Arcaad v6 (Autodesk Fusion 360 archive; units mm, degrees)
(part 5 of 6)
sketch "Sketch11" plane through (6, 0, 0) normal (1, 0, 0) x axis (0, 0, -1)
  line L1 (-2.3267, -33.65) -> (31.3267, -33.65)
  line L2 (-6.5036, -29.6802) -> (-2.6802, -33.5036)
  line L3 (-6.65, 4.3267) -> (-6.65, -29.3267)
  line L4 (-2.6802, 8.5036) -> (-6.5036, 4.6802)
  line L5 (31.3267, 8.65) -> (-2.3267, 8.65)
  line L6 (35.5036, 4.6802) -> (31.6802, 8.5036)
  line L7 (35.65, -29.3267) -> (35.65, 4.3267)
  line L8 (31.6802, -33.5036) -> (35.5036, -29.6802)
  line L9 (287, -585) -> (-13, -585)
  line L10 (287, 15) -> (287, -585)
  line L11 (-13, 15) -> (287, 15)
  line L12 (-13, -585) -> (-13, 15)
  line L13 (21.8852, -461.493) -> (24.8497, -461.493)
  line L14 (24.0039, -461.493) -> (20.4822, -461.493)
  line L15 (24.0039, -465.6319) -> (24.0039, -461.493)
  line L16 (20.4822, -465.5926) -> (20.4822, -461.493)
  line L17 (24.0039, -535.3209) -> (24.0039, -465.6319)
  line L18 (20.4822, -535.3209) -> (20.4822, -461.493)
  line L19 (24.0039, -535.3209) -> (20.4822, -535.3209)
  line L20 (21.8852, -12.9676) -> (21.8852, -557.5324)
  line L21 (24.0039, -60) -> (24.0039, -461.493)
  line L22 (20.4822, -60) -> (20.4822, -461.493)
  line L23 (24.0039, -60) -> (20.4822, -60)
  line L24 (24.0039, -461.493) -> (24.0039, -465.6319)
  line L25 (137, -585) -> (137, 15)
  line L26 (253.5178, -60) -> (253.5178, -461.493)
  line L27 (249.9961, -60) -> (249.9961, -461.493)
  line L28 (249.9961, -60) -> (253.5178, -60)
  line L29 (249.9961, -535.3209) -> (249.9961, -465.6319)
  line L30 (253.5178, -535.3209) -> (253.5178, -461.493)
  line L31 (249.9961, -535.3209) -> (253.5178, -535.3209)
  line L32 (249.9961, -465.6319) -> (249.9961, -461.493)
  line L33 (24.8239, -60) -> (24.8239, -461.493)
  line L34 (18.7522, -60) -> (18.7522, -461.493)
  line L35 (18.7522, -60) -> (24.8239, -60)
  line L36 (24.8239, -535.3209) -> (24.8239, -465.6319)
  line L37 (24.8239, -461.493) -> (24.8239, -465.6319)
  line L38 (18.7522, -535.3209) -> (18.7522, -461.493)
  line L39 (18.7522, -535.3209) -> (24.8239, -535.3209)
  circle C1 centre (161.6956, -62.1445) radius 6.75
  circle C2 centre (200, -65) radius 6.75
  circle C3 centre (109.4135, -81.8008) radius 11.3847
  circle C4 centre (53.9141, -65.8527) radius 6.75
  circle C5 centre (259.5, -557.5) radius 2.5
  circle C6 centre (14.5, -557.5) radius 2.5
  circle C7 centre (259.5, -12.5) radius 11
  arc A1 centre (-2.3267, -33.15) radius 0.5 clockwise from (-2.3267, -33.65) to (-2.6802, -33.5036)
  arc A2 centre (-6.15, -29.3267) radius 0.5 clockwise from (-6.5036, -29.6802) to (-6.65, -29.3267)
  arc A3 centre (-6.15, 4.3267) radius 0.5 clockwise from (-6.65, 4.3267) to (-6.5036, 4.6802)
  arc A4 centre (-2.3267, 8.15) radius 0.5 clockwise from (-2.6802, 8.5036) to (-2.3267, 8.65)
  arc A5 centre (31.3267, 8.15) radius 0.5 clockwise from (31.3267, 8.65) to (31.6802, 8.5036)
  arc A6 centre (35.15, 4.3267) radius 0.5 clockwise from (35.5036, 4.6802) to (35.65, 4.3267)
  arc A7 centre (35.15, -29.3267) radius 0.5 clockwise from (35.65, -29.3267) to (35.5036, -29.6802)
  arc A8 centre (31.3267, -33.15) radius 0.5 clockwise from (31.6802, -33.5036) to (31.3267, -33.65)
  circle C8 centre (45.0775, -139.6703) radius 10
  circle C9 centre (90, -150) radius 10
  circle C10 centre (140.8153, -144.1327) radius 15
  circle C11 centre (130.6535, -184.5454) radius 10
  circle C12 centre (77.0561, -242.5691) radius 7
  circle C13 centre (116.4021, -275.0095) radius 10
  circle C14 centre (220.1507, -225.5922) radius 20
  circle C15 centre (207.9814, -331.3336) radius 20
  circle C16 centre (172.7099, -424.5516) radius 10
  circle C17 centre (125, -350) radius 20
  circle C18 centre (90, -400) radius 15
  circle C19 centre (51.7744, -504.4554) radius 10
  circle C20 centre (140, -490) radius 10
  circle C21 centre (227.7787, -494.7374) radius 10
  circle C22 centre (67.1409, -471.833) radius 20
  circle C23 centre (50.7881, -395.8727) radius 7
  circle C24 centre (140, -390) radius 7
  circle C25 centre (178.2661, -386.7903) radius 15
  circle C26 centre (220, -370) radius 10
  circle C27 centre (181.6604, -262.778) radius 10
  circle C28 centre (123.6741, -235.6181) radius 20
  circle C29 centre (45.7185, -314.2782) radius 10
  circle C30 centre (90.9515, -202.6198) radius 7
  circle C31 centre (227.7787, -136.25) radius 10
  circle C32 centre (182.0487, -124.3724) radius 7
  circle C33 centre (100, -120) radius 7
  circle C34 centre (187.43, -169.7572) radius 20
  circle C35 centre (48.535, -233.4303) radius 10
  circle C36 centre (80, -320) radius 10
  circle C37 centre (173.431, -222.7107) radius 10
  circle C38 centre (200, -300) radius 7
  circle C39 centre (210, -410) radius 7
  circle C40 centre (154.6891, -315.7507) radius 15
  circle C41 centre (60.2066, -358.0992) radius 20
  circle C42 centre (50.4667, -431.8087) radius 15
  circle C43 centre (105.4265, -496.3966) radius 7
  circle C44 centre (185.5991, -468.2067) radius 20
  circle C45 centre (120, -460) radius 7
  circle C46 centre (90, -440) radius 10
  circle C47 centre (135.1235, -425.1239) radius 15
  circle C48 centre (166.6949, -345.8239) radius 7
  circle C49 centre (224.2144, -445.9118) radius 10
  circle C50 centre (223.4596, -269.0631) radius 10
  circle C51 centre (156.0884, -281.9568) radius 7
  circle C52 centre (68.5668, -277.091) radius 15
  circle C53 centre (62.4153, -183.7959) radius 20
  circle C54 centre (230, -180) radius 7
  arc A9 centre (130, -60) radius 6.75 clockwise from (133.8909, -54.4843) to (135.5774, -56.198)
  arc A10 centre (139.0445, -51.0994) radius 6.1658 clockwise from (143.4776, -55.3848) to (135.5774, -56.198)
  arc A11 centre (137.0235, -58.095) radius 7 clockwise from (143.4776, -55.3848) to (134.8099, -64.7357)
  arc A12 centre (130, -60) radius 6.75 clockwise from (134.8099, -64.7357) to (131.7577, -53.4829)
  arc A13 centre (137.0235, -58.095) radius 7 clockwise from (131.7577, -53.4829) to (133.0091, -52.3605)
  arc A14 centre (139.0445, -51.0994) radius 6.1658 clockwise from (133.8909, -54.4843) to (133.0091, -52.3605)
  arc A15 centre (60, -60) radius 7 clockwise from (59.8886, -53.0009) to (65.2927, -55.4188)
  arc A16 centre (56.4567, -67.9193) radius 15.308 clockwise from (59.8886, -53.0009) to (65.2927, -55.4188)
  arc A17 centre (229.981, -95.1972) radius 4.0346 clockwise from (230.2254, -99.2244) to (234.0075, -95.452)
  arc A18 centre (218.2305, -83.4163) radius 19.8437 clockwise from (236.6864, -90.7071) to (234.0075, -95.452)
  arc A19 centre (218.9336, -99.9179) radius 20 clockwise from (236.6864, -90.7071) to (199.0414, -101.992)
  arc A20 centre (185.6453, -91.3697) radius 17.0965 clockwise from (199.0414, -101.992) to (174.847, -78.115)
  arc A21 centre (181.7869, -77.1992) radius 7 clockwise from (174.847, -78.115) to (175.6985, -73.7449)
  arc A22 centre (169.4716, -57.7139) radius 17.1979 clockwise from (181.2794, -70.2176) to (175.6985, -73.7449)
  arc A23 centre (181.7869, -77.1992) radius 7 clockwise from (181.2794, -70.2176) to (188.233, -74.4702)
  arc A24 centre (185.6453, -91.3697) radius 17.0965 clockwise from (188.233, -74.4702) to (202.297, -95.2441)
  arc A25 centre (218.2305, -83.4163) radius 19.8438 clockwise from (230.2254, -99.2244) to (202.297, -95.2441)
  arc A26 centre (143.5424, -81.8008) radius 8.9317 clockwise from (143.9431, -90.7235) to (151.1665, -86.4536)
  arc A27 centre (138.5677, -94.5944) radius 15 clockwise from (151.1665, -86.4536) to (127.5251, -104.7463)
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  point P37 (20.4822, -461.493)
  point P41 (20.4822, -461.493)
  point P38 (24.0039, -461.493)
  point P42 (24.0039, -461.493)
  point P44 (20.4822, -461.493)
  point P47 (20.4822, -461.493)
  point P51 (24.0039, -461.493)
  point P43 (24.0039, -465.6319)
  point P60 (249.9961, -465.6319)
  point P46 (24.0039, -535.3209)
  point P61 (249.9961, -535.3209)
  point P56 (253.5178, -461.493)
  point P48 (20.4822, -535.3209)
  point P62 (253.5178, -535.3209)
  point P58 (249.9961, -461.493)
  point P52 (24.0039, -60)
  point P59 (249.9961, -60)
  point P53 (20.4822, -60)
  point P57 (253.5178, -60)
  coincident P37 P41
  coincident P38 P42
  perpendicular L14 L15
  coincident P37 P44
  perpendicular L14 L16
  parallel L15 L17
  coincident P37 P47
  parallel L17 L18
  perpendicular L17 L19
  coincident P38 P51
  parallel L20 L21
  parallel L20 L22
  perpendicular L21 L23
  symmetric P43 L25 P60
  symmetric P46 L25 P61
  symmetric P47 L25 P56
  symmetric P48 L25 P62
  symmetric P51 L25 P58
  symmetric P52 L25 P59
  symmetric P53 L25 P57
  perpendicular L34 L35
  perpendicular L38 L39
  dimension "d72" = 0.82
  dimension "d73" = -1.73
  dimension "d74" = -0.82
  dimension "d75" = 0.82
  dimension "d76" = 1.73
extrude "Extrude10" cut sketch "Sketch11" profile of L13 L17 L18 L19 L20 L21 L22 L23 L24 L26 L27 L28 L29 L30 L31 L32 L33 L34 L35 L36 L37 L38 L39 against normal blind 6
extrude "Extrude9" cut sketch "Sketch11" profile of L13 L17 L18 L19 L20 L21 L22 L23 L24 against normal blind 6
offset_faces "OffsetFaces2" distance 5
fillet "Fillet3" radius 3
work_plane "WorkPlane3"
mirror "Mirror1"
extrude "Extrude4" add sketch "Sketch3" profile of L7 L9 L10 L11 L12 L13 L15 L16 L17 L18 L19 L20 L21 L22 L23 L24 to an object
sketch "Sketch12" plane through (0, 0, 0) normal (1, 0, 0) x axis (0, 0, -1)
  line L1 (249.9961, -535.3209) -> (249.9961, -60)
  line L2 (249.9961, -60) -> (253.5178, -60)
  line L3 (249.9961, -535.3209) -> (249.9961, -60)
  line L4 (253.5178, -535.3209) -> (249.9961, -535.3209)
  line L5 (253.5178, -60) -> (253.5178, -535.3209)
  line L6 (18.7522, -60) -> (24.8239, -60)
  line L7 (18.7522, -535.3209) -> (18.7522, -60)
  line L8 (24.8239, -535.3209) -> (18.7522, -535.3209)
  line L9 (24.8239, -60) -> (24.8239, -535.3209)
  line L10 (-13, -585) -> (287, -585)
  line L11 (-13, 15) -> (-13, -585)
  line L12 (287, 15) -> (-13, 15)
  line L13 (287, -585) -> (287, 15)
  line L14 (249.1761, -535.3209) -> (249.1761, -60)
  line L15 (255.2478, -60) -> (255.2478, -535.3209)
  line L16 (255.2478, -535.3209) -> (249.1761, -535.3209)
  line L17 (249.1761, -60) -> (255.2478, -60)
  circle C1 centre (161.6956, -62.1445) radius 6.75
  circle C2 centre (200, -65) radius 6.75
  circle C3 centre (109.4135, -81.8008) radius 11.3847
  circle C4 centre (53.9141, -65.8527) radius 6.75
  circle C5 centre (259.5, -557.5) radius 2.5
  circle C6 centre (14.5, -557.5) radius 2.5
  circle C7 centre (259.5, -12.5) radius 2.5
  circle C8 centre (14.5, -12.5) radius 2.5
  arc A1 centre (66.9916, -91.3697) radius 13.5324 clockwise from (56.1847, -83.2249) to (71.1139, -104.2589)
  arc A2 centre (56.4567, -67.9193) radius 15.308 clockwise from (56.1847, -83.2249) to (51.3106, -82.3364)
  arc A3 centre (59.2759, -95.0468) radius 15 clockwise from (71.1139, -104.2589) to (51.3106, -82.3364)
  arc A4 centre (230, -70) radius 6.75 clockwise from (234.5359, -65.0012) to (225.5131, -64.9572)
  arc A5 centre (227.8855, -62.8164) radius 7 clockwise from (220.9494, -63.7597) to (234.5359, -65.0012)
  arc A6 centre (218.2305, -83.4163) radius 19.8438 clockwise from (220.9494, -63.7597) to (225.5131, -64.9572)
  circle C9 centre (45.0775, -139.6703) radius 10
  circle C10 centre (90, -150) radius 10
  circle C11 centre (140.8153, -144.1327) radius 15
  circle C12 centre (130.6535, -184.5454) radius 10
  circle C13 centre (77.0561, -242.5691) radius 7
  circle C14 centre (116.4021, -275.0095) radius 10
  circle C15 centre (220.1507, -225.5922) radius 20
  circle C16 centre (207.9814, -331.3336) radius 20
  circle C17 centre (172.7099, -424.5516) radius 10
  circle C18 centre (125, -350) radius 20
  circle C19 centre (90, -400) radius 15
  circle C20 centre (51.7744, -504.4554) radius 10
  circle C21 centre (140, -490) radius 10
  circle C22 centre (227.7787, -494.7374) radius 10
  circle C23 centre (67.1409, -471.833) radius 20
  circle C24 centre (50.7881, -395.8727) radius 7
  circle C25 centre (140, -390) radius 7
  circle C26 centre (178.2661, -386.7903) radius 15
  circle C27 centre (220, -370) radius 10
  circle C28 centre (181.6604, -262.778) radius 10
  circle C29 centre (123.6741, -235.6181) radius 20
  circle C30 centre (45.7185, -314.2782) radius 10
  circle C31 centre (90.9515, -202.6198) radius 7
  circle C32 centre (227.7787, -136.25) radius 10
  circle C33 centre (182.0487, -124.3724) radius 7
  circle C34 centre (100, -120) radius 7
  arc A7 centre (88.9999, -63.301) radius 6.75 clockwise from (82.2818, -63.9562) to (95.1111, -66.1673)
  arc A8 centre (87.4071, -72.5429) radius 10 clockwise from (77.4095, -72.3278) to (82.2818, -63.9562)
  arc A9 centre (81.2141, -77.1797) radius 6.1658 clockwise from (77.4095, -72.3278) to (84.7984, -82.1966)
  arc A10 centre (87.4071, -72.5429) radius 10 clockwise from (95.1111, -66.1673) to (84.7984, -82.1966)
  arc A11 centre (143.5424, -81.8008) radius 8.9317 clockwise from (143.9431, -90.7235) to (151.1665, -86.4536)
  arc A12 centre (126.5713, -87.0071) radius 17.7649 clockwise from (143.9431, -90.7235) to (127.5251, -104.7463)
  arc A13 centre (138.5677, -94.5944) radius 15 clockwise from (151.1665, -86.4536) to (127.5251, -104.7463)
  circle C35 centre (187.43, -169.7572) radius 20
  circle C36 centre (48.535, -233.4303) radius 10
  circle C37 centre (80, -320) radius 10
  circle C38 centre (173.431, -222.7107) radius 10
  circle C39 centre (200, -300) radius 7
  circle C40 centre (210, -410) radius 7
  circle C41 centre (154.6891, -315.7507) radius 15
  circle C42 centre (60.2066, -358.0992) radius 20
  circle C43 centre (50.4667, -431.8087) radius 15
  circle C44 centre (105.4265, -496.3966) radius 7
  circle C45 centre (185.5991, -468.2067) radius 20
  circle C46 centre (120, -460) radius 7
  circle C47 centre (90, -440) radius 10
  circle C48 centre (135.1235, -425.1239) radius 15
  circle C49 centre (166.6949, -345.8239) radius 7
  circle C50 centre (224.2144, -445.9118) radius 10
  circle C51 centre (223.4596, -269.0631) radius 10
  circle C52 centre (156.0884, -281.9568) radius 7
  circle C53 centre (68.5668, -277.091) radius 15
  circle C54 centre (62.4153, -183.7959) radius 20
  circle C55 centre (230, -180) radius 7
  arc A14 centre (229.981, -95.1972) radius 4.0346 clockwise from (230.2254, -99.2244) to (234.0075, -95.452)
  arc A15 centre (218.2305, -83.4163) radius 19.8438 clockwise from (230.2254, -99.2244) to (202.297, -95.2441)
  arc A16 centre (185.6453, -91.3697) radius 17.0965 clockwise from (188.233, -74.4702) to (202.297, -95.2441)
  arc A17 centre (181.7869, -77.1992) radius 7 clockwise from (181.2794, -70.2176) to (188.233, -74.4702)
  arc A18 centre (169.4716, -57.7139) radius 17.1979 clockwise from (181.2794, -70.2176) to (175.6985, -73.7449)
  arc A19 centre (181.7869, -77.1992) radius 7 clockwise from (174.847, -78.115) to (175.6985, -73.7449)
  arc A20 centre (185.6453, -91.3697) radius 17.0965 clockwise from (199.0414, -101.992) to (174.847, -78.115)
  arc A21 centre (218.9336, -99.9179) radius 20 clockwise from (236.6864, -90.7071) to (199.0414, -101.992)
  arc A22 centre (218.2305, -83.4163) radius 19.8438 clockwise from (236.6864, -90.7071) to (234.0075, -95.452)
  arc A23 centre (56.4567, -67.9193) radius 15.308 clockwise from (59.8886, -53.0009) to (65.2927, -55.4188)
  arc A24 centre (60, -60) radius 7 clockwise from (59.8886, -53.0009) to (65.2927, -55.4188)
  arc A25 centre (130, -60) radius 6.75 clockwise from (133.8909, -54.4843) to (135.5774, -56.198)
  arc A26 centre (139.0445, -51.0994) radius 6.1658 clockwise from (133.8909, -54.4843) to (133.0091, -52.3605)
  arc A27 centre (137.0235, -58.095) radius 7 clockwise from (131.7577, -53.4829) to (133.0091, -52.3605)
  arc A28 centre (130, -60) radius 6.75 clockwise from (134.8099, -64.7357) to (131.7577, -53.4829)
  arc A29 centre (137.0235, -58.095) radius 7 clockwise from (143.4776, -55.3848) to (134.8099, -64.7357)
  arc A30 centre (139.0445, -51.0994) radius 6.1658 clockwise from (143.4776, -55.3848) to (135.5774, -56.198)
  perpendicular L15 L16
  perpendicular L14 L17
  dimension "d77" = 0.82
  dimension "d78" = 1.73
extrude "Extrude11" cut sketch "Sketch12" profile of L1 L3 L5 L14 L15 L16 L17 along normal blind 6
sketch "Sketch1" plane through (0, 0, 0) normal (1, 0, 0) x axis (0, 1, 0)
  line L1
  line L2 (10.6725, 42.0131) -> (-11.493, 42.0131)
  line L3
  line L4 (-10.938, 45.9426) -> (-10.938, 45.9976)
  line L5 (10.6725, 49.1774) -> (10.6725, 46.7526)
  line L6 (10.6725, 44.9776) -> (10.6725, 42.0131)
  line L7 (-11.493, 42.0131) -> (-11.493, 44.9776)
  line L8 (-10.0325, 45.9976) -> (-10.0325, 45.9426)
  line L9 (-11.493, 46.7526) -> (-11.493, 49.1774)
  line L10 (-8.2175, 45.9976) -> (-8.2175, 45.9928)
  line L11 (-8.2175, 45.9928) -> (-8.723, 45.9928)
  line L12 (-8.723, 45.9928) -> (-8.723, 45.9976)
  line L13 (-10.2325, 45.9976) -> (-10.2325, 45.9928)
  line L14 (-10.2325, 45.9928) -> (-10.738, 45.9928)
  line L15 (-10.738, 45.9928) -> (-10.738, 45.9976)
  line L16 (-6.708, 45.9928) -> (-6.708, 45.9976)
  line L17 (-6.2025, 45.9976) -> (-6.2025, 45.9928)
  line L18 (-6.2025, 45.9928) -> (-6.708, 45.9928)
  line L19 (-4.693, 45.9928) -> (-4.693, 45.9976)
  line L20 (-4.1875, 45.9976) -> (-4.1875, 45.9928)
  line L21 (-4.1875, 45.9928) -> (-4.693, 45.9928)
  line L22 (-2.678, 45.9928) -> (-2.678, 45.9976)
  line L23 (-2.1725, 45.9976) -> (-2.1725, 45.9928)
  line L24 (-2.1725, 45.9928) -> (-2.678, 45.9928)
  line L25 (-0.663, 45.9928) -> (-0.663, 45.9976)
  line L26 (-0.1575, 45.9976) -> (-0.1575, 45.9928)
  line L27 (-0.1575, 45.9928) -> (-0.663, 45.9928)
  line L28 (1.352, 45.9928) -> (1.352, 45.9976)
  line L29 (1.8575, 45.9976) -> (1.8575, 45.9928)
  line L30 (1.8575, 45.9928) -> (1.352, 45.9928)
  line L31 (3.367, 45.9928) -> (3.367, 45.9976)
  line L32 (3.8725, 45.9976) -> (3.8725, 45.9928)
  line L33 (3.8725, 45.9928) -> (3.367, 45.9928)
  line L34 (5.382, 45.9928) -> (5.382, 45.9976)
  line L35 (5.8875, 45.9976) -> (5.8875, 45.9928)
  line L36 (5.8875, 45.9928) -> (5.382, 45.9928)
  line L37 (7.397, 45.9928) -> (7.397, 45.9976)
  line L38 (7.9025, 45.9976) -> (7.9025, 45.9928)
  line L39 (7.9025, 45.9928) -> (7.397, 45.9928)
  line L40 (9.412, 45.9928) -> (9.412, 45.9976)
  line L41 (9.9175, 45.9976) -> (9.9175, 45.9928)
  line L42 (9.9175, 45.9928) -> (9.412, 45.9928)
  line L43 (11.427, 45.9928) -> (11.427, 45.9976)
  arc A1 centre (-7.4625, 45.9976) radius 0.755 clockwise from (-8.2175, 45.9976) to (-7.4625, 46.7526)
  arc A2 centre (-9.478, 45.9976) radius 0.755 clockwise from (-9.478, 46.7526) to (-8.723, 45.9976)
  arc A3 centre (-9.4775, 45.9976) radius 0.755 clockwise from (-10.2325, 45.9976) to (-9.4777, 46.7526)
  arc A4 centre (-11.493, 45.9976) radius 0.755 clockwise from (-11.493, 46.7526) to (-10.738, 45.9976)
  arc A5 centre (-7.463, 45.9976) radius 0.755 clockwise from (-7.463, 46.7526) to (-6.708, 45.9976)
  arc A6 centre (-5.4475, 45.9976) radius 0.755 clockwise from (-6.2025, 45.9976) to (-5.4475, 46.7526)
  arc A7 centre (-5.448, 45.9976) radius 0.755 clockwise from (-5.448, 46.7526) to (-4.693, 45.9976)
  arc A8 centre (-3.4325, 45.9976) radius 0.755 clockwise from (-4.1875, 45.9976) to (-3.4325, 46.7526)
  arc A9 centre (-3.433, 45.9976) radius 0.755 clockwise from (-3.433, 46.7526) to (-2.678, 45.9976)
  arc A10 centre (-1.4175, 45.9976) radius 0.755 clockwise from (-2.1725, 45.9976) to (-1.4175, 46.7526)
  arc A11 centre (-1.418, 45.9976) radius 0.755 clockwise from (-1.418, 46.7526) to (-0.663, 45.9976)
  arc A12 centre (0.5975, 45.9976) radius 0.755 clockwise from (-0.1575, 45.9976) to (0.5975, 46.7526)
  arc A13 centre (0.597, 45.9976) radius 0.755 clockwise from (0.597, 46.7526) to (1.352, 45.9976)
  arc A14 centre (2.6125, 45.9976) radius 0.755 clockwise from (1.8575, 45.9976) to (2.6125, 46.7526)
  arc A15 centre (2.612, 45.9976) radius 0.755 clockwise from (2.612, 46.7526) to (3.367, 45.9976)
  arc A16 centre (4.6275, 45.9976) radius 0.755 clockwise from (3.8725, 45.9976) to (4.6275, 46.7526)
  arc A17 centre (4.627, 45.9976) radius 0.755 clockwise from (4.627, 46.7526) to (5.382, 45.9976)
  arc A18 centre (6.6425, 45.9976) radius 0.755 clockwise from (5.8875, 45.9976) to (6.6425, 46.7526)
  arc A19 centre (6.642, 45.9976) radius 0.755 clockwise from (6.642, 46.7526) to (7.397, 45.9976)
  arc A20 centre (8.6575, 45.9976) radius 0.755 clockwise from (7.9025, 45.9976) to (8.6575, 46.7526)
  arc A21 centre (8.657, 45.9976) radius 0.755 clockwise from (8.657, 46.7526) to (9.412, 45.9976)
  arc A22 centre (10.6725, 45.9976) radius 0.755 clockwise from (9.9175, 45.9976) to (10.6725, 46.7526)
  point P92 (-9.4777, 46.7526)
  point P93 (-7.4625, 46.7526)
  point P94 (-5.4475, 46.7526)
  point P95 (-3.4325, 46.7526)
  point P96 (-1.4175, 46.7526)
  point P97 (0.5975, 46.7526)
  point P98 (2.6125, 46.7526)
  point P99 (4.6275, 46.7526)
  point P100 (6.6425, 46.7526)
  point P101 (8.6575, 46.7526)
  point P26 (-6.708, 45.9976)
  tangent L15 A4
  tangent A3 L13
  tangent L12 A2
  tangent A1 L10
  coincident A2 P92
  coincident A5 P93
  coincident A7 P94
  coincident A9 P95
  coincident A11 P96
  coincident A13 P97
  coincident A15 P98
  coincident A17 P99
  coincident A19 P100
  coincident A21 P101
  dimension "d9_2" distance L1 P26 = 1.02
  dimension "d6_1" R-Pattern1-uDistance = 20.15 (= "( 2.015 * 10 ) * 1 mm")
  dimension "d7_1" R-Pattern1-vDistance = 0
extrude "Extrude1" new body sketch "Sketch1" profile of L1 L2 L3 L5 L6 L7 L9 A1 L10 L11 L12 A2 A3 L14 L13 L15 A4 A5 A6 L16 L17 L18 A7 A8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 against normal blind 7 named "d10_2"
sketch "Sketch2" plane through (-7, 0, 0) normal (-1, 0, 0) x axis (0, -1, 0)
  line L1 (-9.412, 45.9976) -> (-9.412, 45.9928)
  line L2 (-7.9025, 45.9928) -> (-7.9025, 45.9976)
  line L3 (-7.397, 45.9928) -> (-7.9025, 45.9928)
  line L4 (-7.397, 45.9976) -> (-7.397, 45.9928)
  line L5 (-5.8875, 45.9928) -> (-5.8875, 45.9976)
  line L6 (-5.382, 45.9928) -> (-5.8875, 45.9928)
  line L7 (-5.382, 45.9976) -> (-5.382, 45.9928)
  line L8 (-3.8725, 45.9928) -> (-3.8725, 45.9976)
  line L9 (-3.367, 45.9928) -> (-3.8725, 45.9928)
  line L10 (-3.367, 45.9976) -> (-3.367, 45.9928)
  line L11 (-1.8575, 45.9928) -> (-1.8575, 45.9976)
  line L12 (-1.352, 45.9928) -> (-1.8575, 45.9928)
  line L13 (-1.352, 45.9976) -> (-1.352, 45.9928)
  line L14 (0.1575, 45.9928) -> (0.1575, 45.9976)
  line L15 (0.663, 45.9928) -> (0.1575, 45.9928)
  line L16 (0.663, 45.9976) -> (0.663, 45.9928)
  line L17 (2.1725, 45.9928) -> (2.1725, 45.9976)
  line L18 (2.678, 45.9928) -> (2.1725, 45.9928)
  line L19 (2.678, 45.9976) -> (2.678, 45.9928)
  line L20 (4.1875, 45.9928) -> (4.1875, 45.9976)
  line L21 (4.693, 45.9928) -> (4.1875, 45.9928)
  line L22 (4.693, 45.9976) -> (4.693, 45.9928)
  line L23 (6.2025, 45.9928) -> (6.2025, 45.9976)
  line L24 (6.708, 45.9928) -> (6.2025, 45.9928)
  line L25 (6.708, 45.9976) -> (6.708, 45.9928)
  line L26 (8.2175, 45.9928) -> (8.2175, 45.9976)
  line L27 (8.723, 45.9928) -> (8.2175, 45.9928)
  line L28 (8.723, 45.9976) -> (8.723, 45.9928)
  line L29 (10.2325, 45.9928) -> (10.2325, 45.9976)
  line L30 (10.738, 45.9928) -> (10.2325, 45.9928)
  line L31 (10.738, 45.9976) -> (10.738, 45.9928)
  line L32 (11.493, 49.1774) -> (11.493, 46.7526)
  line L33
  line L34 (-10.6725, 46.7526) -> (-10.6725, 49.1774)
  line L35 (-9.9175, 45.9928) -> (-9.9175, 45.9976)
  line L36 (-9.412, 45.9928) -> (-9.9175, 45.9928)
  line L37 (-10.6725, 44.9776) -> (-10.6725, 46.7526)
  line L38 (11.493, 44.9776) -> (11.493, 46.7526)
  line L39 (11.493, 44.9776) -> (11.493, 42.0131)
  line L40
  line L41 (-10.6725, 42.0131) -> (-10.6725, 44.9776)
  line L42 (11.493, 42.0131) -> (-10.6725, 42.0131)
  arc A1 centre (-8.657, 45.9976) radius 0.755 clockwise from (-9.412, 45.9976) to (-8.657, 46.7526)
  arc A2 centre (-8.6575, 45.9976) radius 0.755 clockwise from (-8.657, 46.7526) to (-7.9025, 45.9976)
  arc A3 centre (-6.642, 45.9976) radius 0.755 clockwise from (-7.397, 45.9976) to (-6.642, 46.7526)
  arc A4 centre (-6.6425, 45.9976) radius 0.755 clockwise from (-6.642, 46.7526) to (-5.8875, 45.9976)
  arc A5 centre (-4.627, 45.9976) radius 0.755 clockwise from (-5.382, 45.9976) to (-4.627, 46.7526)
  arc A6 centre (-4.6275, 45.9976) radius 0.755 clockwise from (-4.627, 46.7526) to (-3.8725, 45.9976)
  arc A7 centre (-2.612, 45.9976) radius 0.755 clockwise from (-3.367, 45.9976) to (-2.612, 46.7526)
  arc A8 centre (-2.6125, 45.9976) radius 0.755 clockwise from (-2.612, 46.7526) to (-1.8575, 45.9976)
  arc A9 centre (-0.597, 45.9976) radius 0.755 clockwise from (-1.352, 45.9976) to (-0.597, 46.7526)
  arc A10 centre (-0.5975, 45.9976) radius 0.755 clockwise from (-0.597, 46.7526) to (0.1575, 45.9976)
  arc A11 centre (1.418, 45.9976) radius 0.755 clockwise from (0.663, 45.9976) to (1.418, 46.7526)
  arc A12 centre (1.4175, 45.9976) radius 0.755 clockwise from (1.418, 46.7526) to (2.1725, 45.9976)
  arc A13 centre (3.433, 45.9976) radius 0.755 clockwise from (2.678, 45.9976) to (3.433, 46.7526)
  arc A14 centre (3.4325, 45.9976) radius 0.755 clockwise from (3.433, 46.7526) to (4.1875, 45.9976)
  arc A15 centre (5.448, 45.9976) radius 0.755 clockwise from (4.693, 45.9976) to (5.448, 46.7526)
  arc A16 centre (5.4475, 45.9976) radius 0.755 clockwise from (5.448, 46.7526) to (6.2025, 45.9976)
  arc A17 centre (7.463, 45.9976) radius 0.755 clockwise from (6.708, 45.9976) to (7.463, 46.7526)
  arc A18 centre (7.4625, 45.9976) radius 0.755 clockwise from (7.463, 46.7526) to (8.2175, 45.9976)
  arc A19 centre (9.478, 45.9976) radius 0.755 clockwise from (8.723, 45.9976) to (9.4777, 46.7526)
  arc A20 centre (9.4775, 45.9976) radius 0.755 clockwise from (9.4777, 46.7526) to (10.2325, 45.9976)
  arc A21 centre (11.493, 45.9976) radius 0.755 clockwise from (10.738, 45.9976) to (11.493, 46.7526)
  arc A22 centre (-10.6725, 45.9976) radius 0.755 clockwise from (-10.6725, 46.7526) to (-9.9175, 45.9976)
  point P96 (-10.6725, 46.7526)
  point P102 (-10.6725, 46.7526)
  point P101 (-10.6725, 44.9776)
  point P103 (-10.6725, 44.9776)
  point P92 (11.493, 46.7526)
  point P105 (11.493, 46.7526)
  point P104 (11.493, 44.9776)
  point P106 (11.493, 44.9776)
  coincident P96 P102
  coincident P101 P103
  coincident P92 P105
  coincident P104 P106
extrude "Extrude2" add sketch "Sketch2" along normal blind 3 named "d12_2"
sketch "Sketch3" plane through (0, -11.493, 0) normal (0, -1, 0) x axis (1, 0, 0)
  line L1 (0, 44.9776) -> (0, 42.0131)
  line L2 (-7, 44.9776) -> (0, 44.9776)
  line L3 (-7, 46.7526) -> (-7, 44.9776)
  line L4 (0, 46.7526) -> (-7, 46.7526)
  line L5 (0, 49.1774) -> (0, 46.7526)
  line L6 (-10, 49.1774) -> (0, 49.1774)
  line L7 (-10, 42.0131) -> (-10, 49.1774)
  line L8 (0, 42.0131) -> (-10, 42.0131)
  line L9 (-16.5, 42.0131) -> (-10, 42.0131)
  line L10 (-16.5, 48.1131) -> (-10, 48.1131)
  line L11 (-16.5, 42.8589) -> (0, 42.8589)
  line L12 (-16.5, 42.0131) -> (-16.5, 48.1131)
  line L13 (-16.5, 43.8589) -> (0, 43.8589)
  line L14 (-3.509, 42.8589) -> (-3.509, 43.8589)
  line L15 (-18.456, 42.0131) -> (-18.456, 48.1131)
  line L16 (-18.456, 42.0131) -> (-16.5, 42.0131)
  line L17 (-16.5, 48.1131) -> (-18.456, 48.1131)
  line L18 (-16.5, 41.1131) -> (-16.5, 42.0131)
  line L19 (-18.456, 48.4131) -> (-18.456, 48.1131)
  line L20 (-18.456, 41.7131) -> (-18.456, 42.0131)
  line L21 (-16.5, 41.1131) -> (-18.456, 41.7131)
  line L22 (-18.456, 42.8589) -> (-16.5, 42.8589)
  line L23 (-18.456, 46.3806) -> (-10, 46.3806)
  line L24 (-10, 45.2617) -> (-16.5, 45.2459)
  line L25 (-16.5, 49.0131) -> (-16.5, 48.1131)
  line L26 (-16.5, 49.0131) -> (-18.456, 48.4131)
  arc A1 centre (-5.3313, 43.3589) radius 0.5 clockwise from (-5.3313, 43.8589) to (-5.3313, 42.8589)
  arc A2 centre (-10, 45.8212) radius 0.5594 clockwise from (-10, 46.3806) to (-10, 45.2617)
  point P9 (-10, 42.0131)
  point P10 (-10, 42.0131)
  point P14 (0, 42.8589)
  point P15 (-16.5, 42.8589)
  point P18 (-3.509, 43.8589)
  point P19 (-3.509, 42.8589)
  point P26 (-18.456, 42.8589)
  point P27 (-10, 46.3806)
  point P28 (-18.456, 46.3806)
  point P29 (-16.5, 45.2459)
  point P30 (-10, 45.2617)
  point P31 (-5.3313, 43.8589)
  point P32 (-5.3313, 42.8589)
  point P11 (-16.5, 42.0131)
  point P22 (-16.5, 41.1131)
  point P21 (-18.456, 42.0131)
  point P24 (-18.456, 41.7131)
  point P20 (-18.456, 48.1131)
  point P23 (-18.456, 48.4131)
  point P13 (-16.5, 48.1131)
  point P34 (-16.5, 49.0131)
  coincident P9 P10
  perpendicular L7 L9
  coincident L1 P14
  perpendicular L7 L11
  perpendicular L9 L12
  coincident L12 P15
  coincident L13 P18
  coincident L11 P19
  perpendicular L11 L14
  parallel L12 L15
  perpendicular L15 L16
  perpendicular L12 L17
  perpendicular L9 L18
  perpendicular L17 L19
  perpendicular L16 L20
  tangent L11 A1
  coincident L15 P26
  perpendicular L15 L22
  coincident L7 P27
  coincident L15 P28
  perpendicular L15 L23
  coincident L12 P29
  coincident L7 P30
  coincident L13 P31
  coincident L11 P32
  perpendicular L10 L25
  dimension "d14_2" = 6.1
  dimension "d15_1" distance P10 P11 = 6.5
  dimension "d16_2" = 1
  dimension "d18_2" distance P11 P22 = 0.9
  dimension "d19_2" distance P21 P24 = 0.3
  dimension "d20_2" distance P20 P23 = 0.3
  dimension "d27_2" distance P13 P34 = 0.9
extrude "Extrude5" add sketch "Sketch3" profile of L7 L9 L10 L11 L12 L13 L15 L16 L17 L18 L19 L20 L21 L22 L23 L24 L25 L26 to an object
extrude "Extrude3" cut sketch "Sketch3" profile of L7 L11 L13 A1 A2 against normal blind 29 named "d22_2"
sketch "Sketch4" plane through (0, -11.493, 0) normal (0, -1, 0) x axis (1, 0, 0)
  line L1 (-5.3313, 43.8589) -> (-16.5, 43.8589)
  line L2 (-18.456, 42.8589) -> (-5.3313, 42.8589)
  line L3 (-18.456, 41.7131) -> (-18.456, 42.8589)
  line L4 (-16.5, 41.1131) -> (-18.456, 41.7131)
  line L5 (-16.5, 42.0131) -> (-16.5, 41.1131)
  line L6 (0, 42.0131) -> (-16.5, 42.0131)
  line L7 (0, 44.9776) -> (0, 42.0131)
  line L8 (-7, 44.9776) -> (0, 44.9776)
  line L9 (-7, 46.7526) -> (-7, 44.9776)
  line L10 (0, 46.7526) -> (-7, 46.7526)
  line L11 (0, 49.1774) -> (0, 46.7526)
  line L12 (-10, 49.1774) -> (0, 49.1774)
  line L13 (-10, 48.1131) -> (-10, 49.1774)
  line L14 (-16.5, 48.1131) -> (-10, 48.1131)
  line L15 (-16.5, 49.0131) -> (-16.5, 48.1131)
  line L16 (-18.456, 48.4131) -> (-16.5, 49.0131)
  line L17 (-18.456, 46.3806) -> (-18.456, 48.4131)
  line L18 (-10, 46.3806) -> (-18.456, 46.3806)
  line L19 (-16.5, 45.2459) -> (-10, 45.2617)
  line L20 (-16.5, 43.8589) -> (-16.5, 45.2459)
  line L21 (-10, 40.2406) -> (-10, 48.1131)
  line L22 (0.0324, 40.5397) -> (-10, 40.5397)
  line L23 (0, 42.0131) -> (0.0324, 40.5397)
  arc A1 centre (-5.3313, 43.3589) radius 0.5 clockwise from (-5.3313, 43.8589) to (-5.3313, 42.8589)
  arc A2 centre (-10, 45.8212) radius 0.5594 clockwise from (-10, 46.3806) to (-10, 45.2617)
  point P17 (-10, 48.1131)
  point P26 (-10, 48.1131)
  point P28 (-10, 40.5397)
  point P10 (0, 42.0131)
  point P30 (0, 42.0131)
  coincident P17 P26
  perpendicular L6 L21
  coincident L21 P28
  perpendicular L21 L22
  coincident P10 P30
extrude "Extrude6" add sketch "Sketch4" profile of L6 L21 L22 L23 against normal blind 22.165 named "d30_2"
extrude "Extrude7" add of existing geometry blind -2 named "d32_2"
extrude "Extrude8" add of existing geometry blind 0.0005 (= "4.928E-04 mm") named "d34_2"
extrude "Extrude9" cut of existing geometry blind -0.032 named "d36_2"
extrude "Extrude10" cut of existing geometry blind -0.0004 (= "-4.004E-04 mm") named "d38_1"
sketch "Sketch5" plane through (0, -11.493, 0) normal (0, -1, 0) x axis (1, 0, 0)
  line L1 (0, 44.9776) -> (0, 40.5397)
  line L2 (-7, 44.9776) -> (0, 44.9776)
  line L3 (-7, 46.7526) -> (-7, 44.9776)
  line L4 (0, 46.7526) -> (-7, 46.7526)
  line L5 (0, 49.1774) -> (0, 46.7526)
  line L6 (-10, 49.1774) -> (0, 49.1774)
  line L7 (-10, 48.1131) -> (-10, 49.1774)
  line L8 (-16.5, 48.1131) -> (-10, 48.1131)
  line L9 (-16.5, 49.0131) -> (-16.5, 48.1131)
  line L10 (-18.456, 48.4131) -> (-16.5, 49.0131)
  line L11 (-18.456, 46.3806) -> (-18.456, 48.4131)
  line L12 (-10, 46.3806) -> (-18.456, 46.3806)
  line L13 (-16.5, 45.2459) -> (-10, 45.2617)
  line L14 (-16.5, 43.8589) -> (-16.5, 45.2459)
  line L15 (-5.3313, 43.8589) -> (-16.5, 43.8589)
  line L16 (-18.456, 42.8589) -> (-5.3313, 42.8589)
  line L17 (-18.456, 41.7131) -> (-18.456, 42.8589)
  line L18 (-16.5, 41.1131) -> (-18.456, 41.7131)
  line L19 (-16.5, 42.0131) -> (-16.5, 41.1131)
  line L20 (-10, 42.0131) -> (-16.5, 42.0131)
  line L21 (-10, 40.5397) -> (-10, 42.0131)
  line L22 (0, 40.5397) -> (-10, 40.5397)
  line L23 (0.5597, 42.0131) -> (-10, 42.0131)
  line L24 (-7, 39.917) -> (-7, 44.9776)
  arc A1 centre (-10, 45.8212) radius 0.5594 clockwise from (-10, 46.3806) to (-10, 45.2617)
  arc A2 centre (-5.3313, 43.3589) radius 0.5 clockwise from (-5.3313, 43.8589) to (-5.3313, 42.8589)
  point P26 (-10, 42.0131)
  point P28 (-10, 42.0131)
  point P4 (-7, 44.9776)
  point P30 (-7, 44.9776)
  coincident P26 P28
  perpendicular L1 L23
  coincident P4 P30
  perpendicular L22 L24
extrude "Extrude11" cut sketch "Sketch5" profile of L1 L22 L23 L24 against normal blind 28 named "d40_1"
offset_faces "OffsetFaces1" distance 0.6 named "d42_1"
extrude "Extrude12" add of existing geometry blind 0.6 named "d43_1"
fillet "Fillet2" radius 1 named "d45_1"
extrude "Extrude13" add of existing geometry blind 5 named "d46_1"
extrude "Extrude14" add of existing geometry blind 3 named "d48_1"
sketch "Sketch6" plane through (-7, 0, 0) normal (1, 0, 0) x axis (0, 1, 0)
  line L1 (10.6725, 42.0131) -> (10.6725, 32.5397)
  line L2
  line L3 (-11.493, 32.5397) -> (-11.493, 42.0131)
  line L4 (10.6725, 32.5397) -> (-11.493, 32.5397)
  line L5 (-0.4102, 35.5397) -> (-0.4102, 32.5397)
  circle C1 centre (-0.4102, 35.5397) radius 3
  point P6 (-0.4102, 32.5397)
  point P7 (-0.4102, 35.5397)
  point P8 (-0.4102, 35.5397)
  midpoint L4 P6
  perpendicular L4 L5
  coincident P7 P8
  coincident P6 C1
  dimension "d50_1" distance P6 P7 = 3
extrude "Extrude15" add sketch "Sketch6" profile of C1 to an object
sketch "Sketch7" plane through (0, 0, 32.5397) normal (0, 0, -1) x axis (1, 0, 0)
  line L1 (-7, 0.4102) -> (-7, -10.6725)
  line L2 (-7, 11.493) -> (-7, 0.4102)
  line L3 (-10.6, 11.493) -> (-7, 11.493)
  line L4
  line L5 (-7, -10.6725) -> (-10.6, -10.6725)
extrude "Extrude16" add sketch "Sketch7" along normal blind 10 named "d53_1"
move_face "MoveFace1"
move_face "MoveFace2"
offset_faces "OffsetFaces2" distance 0.5 named "d55_1"
sketch "Sketch8" plane through (-7, 0, 0) normal (1, 0, 0) x axis (0, 1, 0)
  line L1 (-11.493, 22.5397) -> (-11.493, 42.0131)
  line L2 (10.6725, 22.5397) -> (-11.493, 22.5397)
  line L3 (10.6725, 32.5397) -> (10.6725, 22.5397)
  line L4 (10.6725, 42.0131) -> (10.6725, 32.5397)
  line L5
  circle C1 centre (-0.3459, 30.5403) radius 3.5
fillet "Fillet3" radius 10 named "d56_1"
sketch "Sketch9" plane through (-10.6, 0, 0) normal (-1, 0, 0) x axis (0, -1, 0)
  line L1 (11.493, 42.0131) -> (11.493, 32.5397)
  line L2
  line L3 (-10.6725, 32.5397) -> (-10.6725, 42.0131)
  line L4 (1.493, 22.5397) -> (-0.6725, 22.5397)
  arc A1 centre (1.493, 32.5397) radius 10 clockwise from (11.493, 32.5397) to (1.493, 22.5397)
  arc A2 centre (-0.6725, 32.5397) radius 10 clockwise from (-0.6725, 22.5397) to (-10.6725, 32.5397)
  circle C1 centre (0.3459, 30.5403) radius 3.5
  circle C2 centre (0.3459, 30.5403) radius 3.25
  concentric C1 C2
  dimension "d57_1" diameter C2 = 6.5
extrude "Extrude17" cut sketch "Sketch9" profile of C2 against normal blind 2.5 named "d58_1"
offset_faces "OffsetFaces3" distance 1 named "d60_1"
offset_faces "OffsetFaces4" distance 0.5 named "d61_1"
sketch "Sketch10" plane through (0.5, 0, 0) normal (1, 0, 0) x axis (0, 1, 0)
  circle C1 centre (-0.3459, 30.5403) radius 3.5
  circle C2 centre (-0.3459, 30.5403) radius 1.65
  concentric C1 C2
  dimension "d62_1" diameter C2 = 3.3
extrude "Extrude18" cut sketch "Sketch10" profile of C2 against normal blind 32 named "d63_1"
position "Position6"
mirror "Mirror1"
extrude "Extrude19" add of existing geometry blind 2.4
extrude "Extrude20" add of existing geometry blind 2.4
extrude "Extrude21" add of existing geometry blind 0 (= "1.951E-05 mm")
extrude "Extrude22" add of existing geometry blind 2.4
extrude "Extrude23" add of existing geometry blind 2.4
component_insert "Component Insert9"
position "Position7"
mirror_component "MirrorComponent1"
derived_instance "DerivedInstance1"
sketch "Sketch13" plane through (0, 0, 0) normal (-1, 0, 0) x axis (0, 0, 1)
  line L1 (13, -585) -> (-287, -585)
  line L2 (13, 15) -> (13, -585)
  line L3 (-287, 15) -> (13, 15)
  line L4 (-287, -585) -> (-287, 15)
  line L5 (-18.7522, -60) -> (-24.8239, -60)
  line L6 (-18.7522, -535.3209) -> (-18.7522, -60)
  line L7 (-24.8239, -535.3209) -> (-18.7522, -535.3209)
  line L8 (-24.8239, -60) -> (-24.8239, -535.3209)
  line L9 (-249.1761, -60) -> (-255.2478, -60)
  line L10 (-249.1761, -535.3209) -> (-249.1761, -60)
  line L11 (-255.2478, -535.3209) -> (-249.1761, -535.3209)
  line L12 (-255.2478, -60) -> (-255.2478, -535.3209)
  line L13 (-239.7373, -559.8874) -> (-242.6873, -559.8874)
  line L14 (-239.3373, -556.9874) -> (-239.3373, -559.4874)
  line L15 (-243.0873, -559.4874) -> (-243.0873, -556.9874)
  line L16 (-232.6873, -559.4874) -> (-232.6873, -556.9874)
  line L17 (-229.3373, -559.8874) -> (-232.2873, -559.8874)
  line L18 (-228.9373, -556.9874) -> (-228.9373, -559.4874)
  arc A1 centre (-130, -60) radius 6.75 clockwise from (-135.5774, -56.198) to (-133.8909, -54.4843)
  arc A2 centre (-139.0445, -51.0994) radius 6.1658 clockwise from (-133.0091, -52.3605) to (-133.8909, -54.4843)
  arc A3 centre (-137.0235, -58.095) radius 7 clockwise from (-133.0091, -52.3605) to (-131.7577, -53.4829)
  arc A4 centre (-130, -60) radius 6.75 clockwise from (-131.7577, -53.4829) to (-134.8099, -64.7357)
  arc A5 centre (-137.0235, -58.095) radius 7 clockwise from (-134.8099, -64.7357) to (-143.4776, -55.3848)
  arc A6 centre (-139.0445, -51.0994) radius 6.1658 clockwise from (-135.5774, -56.198) to (-143.4776, -55.3848)
  circle C1 centre (-161.6956, -62.1445) radius 6.75
  circle C2 centre (-200, -65) radius 6.75
  circle C3 centre (-109.4135, -81.8008) radius 11.3847
  circle C4 centre (-53.9141, -65.8527) radius 6.75
  arc A7 centre (-56.4567, -67.9193) radius 15.308 clockwise from (-65.2927, -55.4188) to (-59.8886, -53.0009)
  arc A8 centre (-60, -60) radius 7 clockwise from (-65.2927, -55.4188) to (-59.8886, -53.0009)
  arc A9 centre (-229.981, -95.1972) radius 4.0346 clockwise from (-234.0075, -95.452) to (-230.2254, -99.2244)
  arc A10 centre (-218.2305, -83.4163) radius 19.8438 clockwise from (-202.297, -95.2441) to (-230.2254, -99.2244)
  arc A11 centre (-185.6453, -91.3697) radius 17.0965 clockwise from (-202.297, -95.2441) to (-188.233, -74.4702)
  arc A12 centre (-181.7869, -77.1992) radius 7 clockwise from (-188.233, -74.4702) to (-181.2794, -70.2176)
  arc A13 centre (-169.4716, -57.7139) radius 17.1979 clockwise from (-175.6985, -73.7449) to (-181.2794, -70.2176)
  arc A14 centre (-181.7869, -77.1992) radius 7 clockwise from (-175.6985, -73.7449) to (-174.847, -78.115)
  arc A15 centre (-185.6453, -91.3697) radius 17.0965 clockwise from (-174.847, -78.115) to (-199.0414, -101.992)
  arc A16 centre (-218.9336, -99.9179) radius 20 clockwise from (-199.0414, -101.992) to (-236.6864, -90.7071)
  arc A17 centre (-218.2305, -83.4163) radius 19.8438 clockwise from (-234.0075, -95.452) to (-236.6864, -90.7071)
  circle C5 centre (-230, -180) radius 7
  circle C6 centre (-62.4153, -183.7959) radius 20
  circle C7 centre (-68.5668, -277.091) radius 15
  circle C8 centre (-156.0884, -281.9568) radius 7
  circle C9 centre (-223.4596, -269.0631) radius 10
  circle C10 centre (-224.2144, -445.9118) radius 10
  circle C11 centre (-166.6949, -345.8239) radius 7
  circle C12 centre (-135.1235, -425.1239) radius 15
  circle C13 centre (-90, -440) radius 10
  circle C14 centre (-120, -460) radius 7
  circle C15 centre (-185.5991, -468.2067) radius 20
  circle C16 centre (-105.4265, -496.3966) radius 7
  circle C17 centre (-50.4667, -431.8087) radius 15
  circle C18 centre (-60.2066, -358.0992) radius 20
  circle C19 centre (-154.6891, -315.7507) radius 15
  circle C20 centre (-210, -410) radius 7
  circle C21 centre (-200, -300) radius 7
  circle C22 centre (-173.431, -222.7107) radius 10
  circle C23 centre (-80, -320) radius 10
  circle C24 centre (-48.535, -233.4303) radius 10
  circle C25 centre (-187.43, -169.7572) radius 20
  arc A18 centre (-143.5424, -81.8008) radius 8.9317 clockwise from (-151.1665, -86.4536) to (-143.9431, -90.7235)
  arc A19 centre (-126.5713, -87.0071) radius 17.7649 clockwise from (-127.5251, -104.7463) to (-143.9431, -90.7235)
  arc A20 centre (-138.5677, -94.5944) radius 15 clockwise from (-127.5251, -104.7463) to (-151.1665, -86.4536)
  arc A21 centre (-88.9999, -63.301) radius 6.75 clockwise from (-95.1111, -66.1673) to (-82.2818, -63.9562)
  arc A22 centre (-87.4071, -72.5429) radius 10 clockwise from (-82.2818, -63.9562) to (-77.4095, -72.3278)
  arc A23 centre (-81.2141, -77.1797) radius 6.1658 clockwise from (-84.7984, -82.1966) to (-77.4095, -72.3278)
  arc A24 centre (-87.4071, -72.5429) radius 10 clockwise from (-84.7984, -82.1966) to (-95.1111, -66.1673)
  circle C26 centre (-100, -120) radius 7
  circle C27 centre (-182.0487, -124.3724) radius 7
  circle C28 centre (-227.7787, -136.25) radius 10
  circle C29 centre (-90.9515, -202.6198) radius 7
  circle C30 centre (-45.7185, -314.2782) radius 10
  circle C31 centre (-123.6741, -235.6181) radius 20
  circle C32 centre (-181.6604, -262.778) radius 10
  circle C33 centre (-220, -370) radius 10
  circle C34 centre (-178.2661, -386.7903) radius 15
  circle C35 centre (-140, -390) radius 7
  circle C36 centre (-50.7881, -395.8727) radius 7
  circle C37 centre (-67.1409, -471.833) radius 20
  circle C38 centre (-227.7787, -494.7374) radius 10
  circle C39 centre (-140, -490) radius 10
  circle C40 centre (-51.7744, -504.4554) radius 10
  circle C41 centre (-90, -400) radius 15
  circle C42 centre (-125, -350) radius 20
  circle C43 centre (-172.7099, -424.5516) radius 10
  circle C44 centre (-207.9814, -331.3336) radius 20
  circle C45 centre (-220.1507, -225.5922) radius 20
  circle C46 centre (-116.4021, -275.0095) radius 10
  circle C47 centre (-77.0561, -242.5691) radius 7
  circle C48 centre (-130.6535, -184.5454) radius 10
  circle C49 centre (-140.8153, -144.1327) radius 15
  circle C50 centre (-90, -150) radius 10
  circle C51 centre (-45.0775, -139.6703) radius 10
  circle C52 centre (-259.5, -557.5) radius 2.5
  circle C53 centre (-14.5, -557.5) radius 2.5
  circle C54 centre (-259.5, -12.5) radius 2.5
  circle C55 centre (-14.5, -12.5) radius 2.5
  arc A25 centre (-230, -70) radius 6.75 clockwise from (-225.5131, -64.9572) to (-234.5359, -65.0012)
  arc A26 centre (-227.8855, -62.8164) radius 7 clockwise from (-234.5359, -65.0012) to (-220.9494, -63.7597)
  arc A27 centre (-218.2305, -83.4163) radius 19.8437 clockwise from (-225.5131, -64.9572) to (-220.9494, -63.7597)
  arc A28 centre (-66.9916, -91.3697) radius 13.5324 clockwise from (-71.1139, -104.2589) to (-56.1847, -83.2249)
  arc A29 centre (-56.4567, -67.9193) radius 15.308 clockwise from (-51.3106, -82.3364) to (-56.1847, -83.2249)
  arc A30 centre (-59.2759, -95.0468) radius 15 clockwise from (-51.3106, -82.3364) to (-71.1139, -104.2589)
  arc A31 centre (-242.6873, -559.4874) radius 0.4 clockwise from (-242.6873, -559.8874) to (-243.0873, -559.4874)
  arc A32 centre (-239.7373, -559.4874) radius 0.4 clockwise from (-239.3373, -559.4874) to (-239.7373, -559.8874)
  arc A33 centre (-241.2123, -556.9874) radius 1.875 clockwise from (-243.0873, -556.9874) to (-239.3373, -556.9874)
  circle C56 centre (-241.2123, -556.9874) radius 1.475
  arc A34 centre (-230.8123, -556.9874) radius 1.875 clockwise from (-232.6873, -556.9874) to (-228.9373, -556.9874)
  arc A35 centre (-232.2873, -559.4874) radius 0.4 clockwise from (-232.2873, -559.8874) to (-232.6873, -559.4874)
  arc A36 centre (-229.3373, -559.4874) radius 0.4 clockwise from (-228.9373, -559.4874) to (-229.3373, -559.8874)
  circle C57 centre (-230.8123, -556.9874) radius 1.475
  circle C58 centre (-43.1877, -556.9874) radius 1.475
  circle C59 centre (-43.1877, -556.9874) radius 1.475
  circle C60 centre (-32.7877, -556.9874) radius 1.475
  circle C61 centre (-32.7877, -556.9874) radius 1.475
extrude "Extrude12" cut sketch "Sketch13" profile of C56 C57 C58 C59 C60 C61 against normal blind 80
sketch "Sketch14" plane through (-4.6, 0, 0) normal (-1, 0, 0) x axis (0, 0, 1)
  line L1 (-249.1503, -420.4241) -> (-239.6769, -420.4241)
  line L2
  line L3 (-239.6769, -442.5896) -> (-249.1503, -442.5896)
  line L4 (-24.8497, -442.5896) -> (-34.3231, -442.5896)
  line L5 (-24.8497, -420.4241) -> (-24.8497, -442.5896)
  line L6 (-34.3231, -420.4241) -> (-24.8497, -420.4241)
  line L7 (-34.3231, -420.4241) -> (-239.6769, -420.4241)
  line L8 (-239.6769, -442.5896) -> (-34.3231, -442.5896)
  line L9
  line L10 (-237.6775, -420.4241) -> (-237.6775, -431.5712)
  line L11
  line L12
  line L13 (-242.2892, -439.5896) -> (-31.7108, -439.5896)
  line L14 (-31.942, -423.4241) -> (-242.058, -423.4241)
  line L15
  line L16
  line L17 (-237.6775, -410.4241) -> (-237.6775, -420.4241)
  line L18 (-232, -408.4241) -> (-235.6775, -408.4241)
  line L19 (-230, -417) -> (-230, -410.4241)
  line L20 (-44, -417) -> (-44, -410.4241)
  line L21 (-36.3225, -410.4241) -> (-36.3225, -420.4241)
  line L22 (-42, -408.4241) -> (-38.3225, -408.4241)
  circle C1 centre (-237.6775, -431.5712) radius 3.5
  circle C2 centre (-36.3225, -431.5712) radius 3.5
  arc A1 centre (-36.3225, -431.5712) radius 9.25 clockwise from (-31.942, -423.4241) to (-31.7108, -439.5896)
  arc A2 centre (-237.6775, -431.5712) radius 9.25 clockwise from (-242.2892, -439.5896) to (-242.058, -423.4241)
  circle C3 centre (-237.6775, -431.5712) radius 3.8
  circle C4 centre (-36.3225, -431.5712) radius 3.8
  arc A3 centre (-226.3146, -417) radius 3.6854 clockwise from (-227.6775, -420.4241) to (-230, -417)
  arc A4 centre (-232, -410.4241) radius 2 clockwise from (-232, -408.4241) to (-230, -410.4241)
  arc A5 centre (-235.6775, -410.4241) radius 2 clockwise from (-237.6775, -410.4241) to (-235.6775, -408.4241)
  arc A6 centre (-47.6854, -417) radius 3.6854 clockwise from (-44, -417) to (-46.3225, -420.4241)
  arc A7 centre (-38.3225, -410.4241) radius 2 clockwise from (-38.3225, -408.4241) to (-36.3225, -410.4241)
  arc A8 centre (-42, -410.4241) radius 2 clockwise from (-44, -410.4241) to (-42, -408.4241)
  point P2 (-239.6769, -420.4241)
  point P12 (-239.6769, -420.4241)
  point P7 (-34.3231, -420.4241)
  point P13 (-34.3231, -420.4241)
  point P8 (-34.3231, -442.5896)
  point P14 (-34.3231, -442.5896)
  point P5 (-239.6769, -442.5896)
  point P15 (-239.6769, -442.5896)
  point P17 (-137, -420.4241)
  point P18 (-137, -442.5896)
  point P16 (-237.6775, -431.5712)
  point P20 (-237.6775, -431.5712)
  point P21 (-237.6775, -420.4241)
  point P22 (-237.6775, -442.5896)
  point P23 (-36.3225, -420.4241)
  point P24 (-36.3225, -442.5896)
  point P29 (-46.3225, -420.4241)
  point P30 (-46.3225, -442.5896)
  point P35 (-237.6775, -408.4241)
  point P19 (-36.3225, -431.5712)
  coincident P2 P12
  coincident P7 P13
  coincident P8 P14
  coincident P5 P15
  concentric C1 A2
  midpoint L7 P17
  midpoint L8 P18
  coincident P16 P20
  perpendicular L7 L10
  vertical L11
  coincident L7 P21
  coincident L8 P22
  coincident L7 P23
  coincident L8 P24
  perpendicular L8 L12
  parallel L7 L14
  parallel L8 L13
  coincident L7 P29
  coincident L8 P30
  perpendicular L8 L15
  concentric C1 C3
  concentric C2 C4
  perpendicular L17 L18
  perpendicular L7 L19
  tangent L19 A3
  tangent L18 A4
  tangent L19 A4
  coincident P35 L17
  coincident P35 L18
  tangent L17 A5
  tangent L18 A5
  equal A4 A5
  dimension "d222" diameter A2 = 18.5
  dimension "d225" distance P19 L15 = 10
  dimension "d228" diameter C1 = 7
  dimension "d229" diameter C3 = 7.6
  dimension "d230" diameter C4 = 7.6
  dimension "d246" distance P21 P35 = 12
  dimension "d247" radius A4 = 2
extrude "Extrude24" new body sketch "Sketch14" profile of L7 L8 L9 A1 L10 L11 L12 L13 L14 L15 C4 L16 L17 L18 L19 A3 A4 A5 A6 L20 L21 A7 L22 A8 along normal blind 3
component_from_bodies "Body->Comp"
copy_paste "CutPaste"
extrude "Extrude13" new body sketch "Sketch14" profile of A2 L9 L10 L11 L13 L14 C3 along normal blind 3
extrude "Extrude14" new body sketch "Sketch14" profile of L7 L8 L9 L13 L14 L15 L16 against normal blind 3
